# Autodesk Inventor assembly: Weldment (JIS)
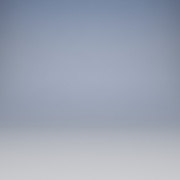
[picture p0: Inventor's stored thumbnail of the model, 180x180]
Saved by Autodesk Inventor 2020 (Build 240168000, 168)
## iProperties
Length Units: 11269
Angle Units: 11283
Time Units: 11279
Mass Units: 11290
Length Display Precision: 3
Angle Display Precision: 2
Part Number: Weldment (JIS)
Document SubType Name: Weldment
Created: 2002-06
Designer: smithga
Created: 2002-08
Weld Material: Welded Aluminum-6061
Manager: www.cadconsulting.pl
Company: Fabian Stasiak CAD Consulting
Control State: 0
Master: False
Shininess: 64.0
Angle Units: 11279
Time Units: 11290
Mass Units: 11283
Compacted: True
Density: 0.0
Volumn: 0.0
Area: 0.0
PropertySet Name: Model Information
Author: F.Stasiak
Subject: Zbiór ćwiczeń. Autodesk Inventor 2020. Kurs podstawowy
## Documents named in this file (1)
- M:\AUTOBUILD\M24_168_RTM\Application\App\Templates\en-US\Metric\Weldment (JIS).iam
